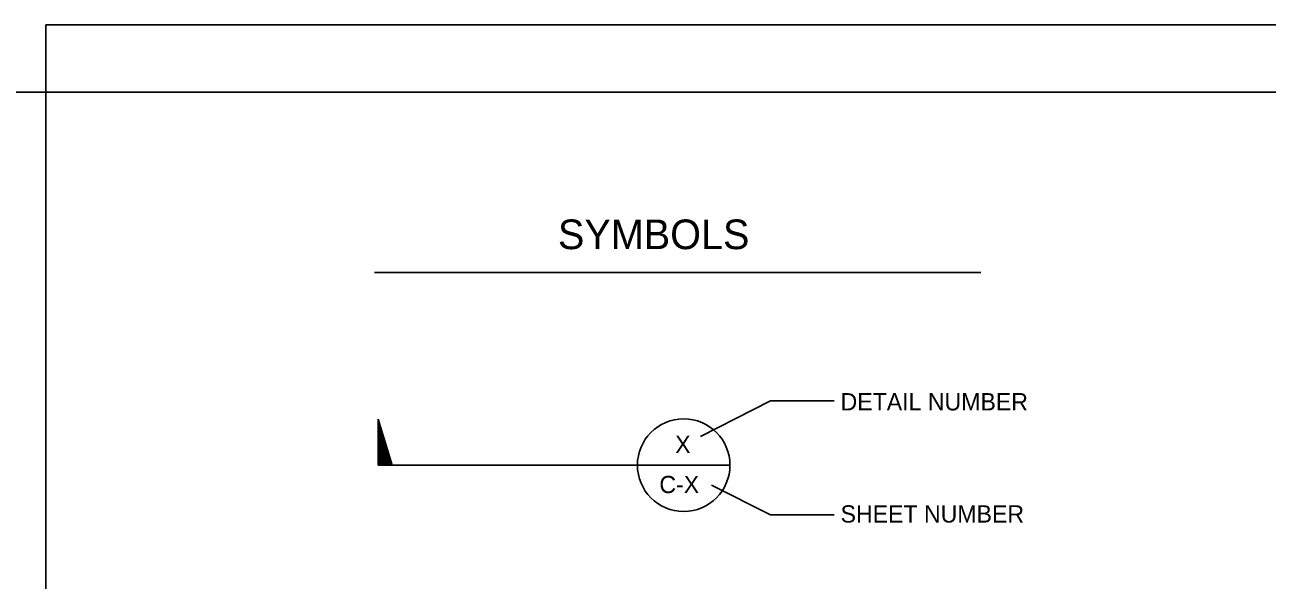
# Model space of a CAD drawing. Extents: x 6711682 to 6713077, y 1869209 to 1870525.
# Drawn here: x 6712022 to 6712525, y 1870300 to 1870525 of the extents above; entities that cross this region are included whole.
import ezdxf

# ---------------------------------------------------------------- set-up
doc = ezdxf.new("R2010")
doc.units = 0
for name, color, linetype in [('Control (1)', 7, 'Continuous'), ('G-TTLB-VIEW', 7, 'Continuous'), ('Nongeo Data(60)', 7, 'Continuous'), ('Sheet Format(10)', 7, 'Continuous')]:
    doc.layers.add(name, color=color, linetype=linetype)

msp = doc.modelspace()

# ---------------------------------------------------------------- linework, layer by layer
at = {"layer": 'Control (1)'}
for p, q in [((6712295.7, 1870357.93), (6712324.02, 1870372.44)), ((6712324.02, 1870372.44), (6712349.93, 1870372.44)), ((6712165.05, 1870346.32), (6712165.05, 1870364.94)), ((6712165.05, 1870364.94), (6712170.76, 1870346.32)), ((6712170.32, 1870346.32), (6712165.05, 1870363.5)), ((6712165.05, 1870361.8), (6712169.8, 1870346.32)), ((6712169.36, 1870346.32), (6712165.05, 1870360.39)), ((6712165.05, 1870358.55), (6712168.8, 1870346.32)), ((6712168.22, 1870346.32), (6712165.05, 1870356.66)), ((6712165.05, 1870355.06), (6712167.73, 1870346.32)), ((6712167.06, 1870346.32), (6712165.05, 1870352.85)), ((6712165.05, 1870351.23), (6712166.56, 1870346.32)), ((6712165.92, 1870346.32), (6712165.05, 1870349.15)), ((6712165.05, 1870347.6), (6712165.45, 1870346.32)), ((6712270.14, 1870346.32), (6712165.05, 1870346.32)), ((6712269.94, 1870346.27), (6712307.64, 1870346.27)), ((6712300.14, 1870338.28), (6712324.02, 1870326.14)), ((6712324.02, 1870326.14), (6712349.93, 1870326.14))]:
    msp.add_line(p, q, dxfattribs=at)
msp.add_circle((6712288.89, 1870346.32), 18.75, dxfattribs=at)
at = {"layer": 'G-TTLB-VIEW'}
for points in [[(6712030.32, 1870524.68), (6712727.83, 1870524.68), (6712727.83, 1869964.67), (6712030.32, 1869964.67)], [(6711681.56, 1870497.47), (6713076.58, 1870497.47), (6713076.58, 1869377.45), (6711681.56, 1869377.45)]]:
    msp.add_lwpolyline(points, close=True, dxfattribs=at)
at = {"layer": 'Nongeo Data(60)'}
msp.add_line((6712163.57, 1870424.32), (6712409.26, 1870424.32), dxfattribs=at)

# ---------------------------------------------------------------- texts
msp.add_text('SYMBOLS', height=12, rotation=0, dxfattribs=at).set_placement((6712237.94, 1870433.83))
at = {"layer": 'Sheet Format(10)'}
for s, p in [('DETAIL NUMBER', (6712352.47, 1870368.51)), ('X', (6712285.44, 1870351.23)), ('C-X', (6712279.04, 1870334.99)), ('SHEET NUMBER', (6712352.47, 1870323.07))]:
    msp.add_text(s, height=7, dxfattribs=at).set_placement(p)

doc.saveas('drawing.dxf')
